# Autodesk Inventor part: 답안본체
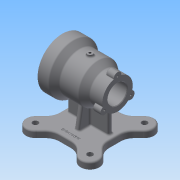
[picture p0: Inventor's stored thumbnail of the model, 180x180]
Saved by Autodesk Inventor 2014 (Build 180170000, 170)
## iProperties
Created: 2017-03
Part Number: 답안본체
Material: 일반
Document SubType Name: Modeling
Designer: NET
Density: 1 g/cm^3
Appearance: 기본값
Author: NET
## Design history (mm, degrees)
sketch "스케치2"
  geometry: L1 (0, 70)-(0, -70); L2 (-70, 0)-(70, 0); L3 (-49.497, -49.497)-(49.497, 49.497); L4 (49.497, -49.497)-(-49.497, 49.497); L5 (-52.322, 28.281)-(-61.518, 37.477); L6 (-28.281, 52.322)-(-37.477, 61.518); L7 (-61.518, -37.477)-(-52.322, -28.281); L8 (-37.477, -61.518)-(-28.281, -52.322); L9 (0, 0)-(45, 0); L10 (0, 0)-(0, -45); L11 (-10.603, 45)-(10.603, 45); L12 (45, 10.603)-(45, -10.603); L13 (10.603, -45)-(-10.603, -45); L14 (-45, -10.603)-(-45, 10.603); L15 (-45, 45)-(45, -45); L16 (45, 45)-(-45, -45); L17 (28.281, 52.322)-(37.477, 61.518); L18 (28.281, -52.322)-(35.995, -60.036); L19 (61.518, -37.477)-(52.322, -28.281); L20 (52.322, 28.281)-(61.518, 37.477); A1 r 17 centre (-49.497, 49.497) between (-36.106, 59.97) and (-59.97, 36.106); A2 r 17 centre (-49.497, -49.497) between (-59.97, -36.106) and (-36.106, -59.97); A3 r 17 centre (49.497, -49.497) between (36.106, -59.97) and (59.97, -36.106); A4 r 17 centre (49.497, 49.497) between (59.97, 36.106) and (36.106, 59.97); A5 r 25 centre (-70, 10.603) between (-45, 10.603) and (-52.322, 28.281); A6 r 25 centre (-70, -10.603) between (-52.322, -28.281) and (-45, -10.603); A7 r 25 centre (-10.603, 70) between (-28.281, 52.322) and (-10.603, 45); A8 r 25 centre (-10.603, -70) between (-10.603, -45) and (-28.281, -52.322); A9 r 25 centre (10.603, 70) between (10.603, 45) and (28.281, 52.322); A10 r 25 centre (10.603, -70) between (28.281, -52.322) and (10.603, -45); A11 r 25 centre (70, -10.603) between (45, -10.603) and (52.322, -28.281); A12 r 25 centre (70, 10.603) between (52.322, 28.281) and (45, 10.603); A13 r 70 centre (0, 0) between (-35.995, 60.036) and (-60.036, 35.995); A14 r 70 centre (0, 0) between (60.036, 35.995) and (35.995, 60.036); A15 r 70 centre (0, 0) between (-60.036, -35.995) and (-35.995, -60.036); A16 r 70 centre (0, 0) between (35.995, -60.036) and (60.036, -35.995); 1 further point
  constraints: 44 point on circle, 40 end point, 18 point on line, 16 centre point, 16 tangent, 10 parallel, 5 coincident, 4 equal radius, 4 midpoint, 2 perpendicular, 1 horizontal, 1 vertical
  dimensions: "d25" = 140 distance of L1.start L1.end; "d26" = 140 distance of L2.start L2.end; "d27" = 45 deg angle of L1 L3; "d28" = 45 deg angle of L1 L4; "d29" = 34 diameter of A1; "d30" = 34 diameter of A2; "d31" = 34 diameter of A3; "d32" = 34 diameter of A4; "d33" = 17 distance between parallel lines of L4 L5; "d34" = 17 distance between parallel lines of L6 L4; "d35" = 17 distance between parallel lines of L7 L3; "d36" = 17 distance between parallel lines of L8 L3; "d37" = 45 distance of L9.start L9.end; "d38" = 45 distance of L9.start L10.end; "d39" = 90 distance of L15.start L16.start; "d40" = 25 radius of A5; "d41" = 17 distance between parallel lines of L19 L4; "d42" = 17 distance between parallel lines of L18 L15; "d43" = 17 distance between parallel lines of L17 L3; "d44" = 25 radius of A9; "d45" = 25 radius of A10; "d46" = 17 distance between parallel lines of L20 L3; "d47" = 25 radius of A12; "d48" = 45 distance between parallel lines of L13 L2; "d49" = 98.99495 horizontal distance of A4.centre A2.centre; "d50" = 98.99495 horizontal distance of A1.centre A3.centre; "d51" = 98.99495 distance of A3.centre A4.centre; "d52" = 70 radius of A16; "d53" = 45 distance between parallel lines of L14 L1
extrude "돌출1" new body sketch "스케치2" distance "d54" = 12; taper "d55" = 0 deg
node "작업 평면1"
sketch "스케치3"
  geometry: L1 (-55.894, 0)-(-55.894, 12) reference; L2 (77.101, 0)-(77.101, 12) reference; L3 (10.603, 0)-(10.603, 82); L4 (10.603, 82)-(-39.397, 82); L5 (-39.397, 82)-(-39.397, 127); L6 (-39.397, 127)-(-19.397, 127); L7 (10.603, 82)-(60.603, 82); L8 (60.603, 82)-(60.603, 109.5); L9 (-39.397, 82)-(-8.397, 82); L10 (-8.397, 118)-(-19.397, 127); L11 (60.603, 109.5)-(37.603, 109.5); L12 (-39.397, 82)-(25.603, 82); L13 (25.603, 118)-(-8.397, 118); L14 (25.603, 118)-(37.603, 109.5); L15 (-39.397, 82)-(-16.397, 82); L16 (-16.397, 82)-(-16.397, 114); L17 (-19.397, 117)-(-39.397, 117); L18 (-8.397, 117)-(-8.397, 118); L19 (60.603, 82)-(30.603, 82); L20 (30.603, 82)-(30.603, 99.5); L21 (33.603, 99.5)-(60.603, 99.5); L22 (-16.397, 82)-(-16.397, 105); L23 (-13.397, 108)-(27.603, 108); L24 (30.603, 105)-(30.603, 82); A1 r 3 centre (-19.397, 114) between (-16.397, 114) and (-19.397, 117); A2 r 3 centre (-13.397, 105) between (-13.397, 108) and (-16.397, 105); A3 r 3 centre (27.603, 105) between (30.603, 105) and (27.603, 108); A4 r 3 centre (33.603, 102.5) between (30.603, 102.5) and (33.603, 99.5); 2 further points
  constraints: 44 end point, 15 point on line, 10 perpendicular, 8 point on circle, 8 tangent, 5 parallel, 4 centre point, 2 equal radius
  dimensions: "d56" = 82 distance of L3.start L3.end; "d57" = 50 distance of L3.end L4.end; "d58" = 45 distance of L4.end L5.end; "d59" = 20 distance of L5.end L6.end; "d60" = 50 distance of L3.end L7.end; "d61" = 27.5 distance of L7.end L8.end; "d62" = 31 distance of L4.end L9.end; "d63" = 36 distance of L9.end L10.start; "d64" = 23 distance of L8.end L11.end; "d65" = 65 distance of L4.end L12.end; "d66" = 23 distance of L4.end L15.end; "d67" = 35 distance of L15.end point (-16.397, 117); "d68" = 36 distance between parallel lines of L12 L13; "d69" = 12 horizontal distance of L13.start L11.end; "d70" = 30 distance of L19.end L7.end; "d71" = 17.5 distance of L19.end L20.end; "d72" = 26 distance of L15.end point (-16.397, 108); "d73" = 3 radius of A1; "d74" = 3 radius of A4
revolve "회전1" sketch "스케치3" stored, may be unused: angle "d75" = 90 deg
sketch "스케치4" dims "d76" = 80
  geometry: C1 r 45 at (0, 0) reference; C2 r 2.5 at (40, 0); C3 r 2.5 at (20, 34.641); C4 r 2.5 at (-20, 34.641); C5 r 2.5 at (-40, 0); C6 r 2.5 at (-20, -34.641); C7 r 2.5 at (20, -34.641); 2 further points
  constraints: 6 centre point, 1 coincident, 1 horizontal alignment, 15 other
  dimensions: "d77" = 5 diameter of C2; "d80" = 360 deg dimension on point (0, 0) C2.centre (derived); "d82" = 34.64102 vertical distance of C2.centre C3.centre
hole "구멍1" sketch "스케치4" at (-40, 0), (-20, -34.641), (20, -34.641), (40, 0), (20, 34.641), (-20, 34.641) diameter "d83" = 3.242; stored, may be unused: countersink angle "d87" = 90 deg, drill point angle "d89" = 118 deg; dims "d84" = 9, "d85" = 4, "d86" = 2, "d88" = 11
node "작업 평면3"
  node "작업 평면2"
sketch "스케치5"
  geometry: C1 r 5 at (0, 0); 1 further point
  constraints: 1 centre point, 1 coincident
  dimensions: "d92" = 10 diameter of C1
extrude "돌출2" join sketch "스케치5" stored distance "d93" = 12; taper "d94" = 0 deg
sketch "스케치6"
  geometry: C1 r 5 at (0, 0) reference; C2 r 2.5 at (0, 0)
  constraints: 1 centre point, 1 coincident
  dimensions: "d95" = 5 diameter of C2
hole "구멍2" sketch "스케치6" at (0, 0) diameter "d96" = 4.134; stored, may be unused: countersink angle "d100" = 90 deg, drill point angle "d102" = 118 deg; dims "d97" = 9, "d98" = 4, "d99" = 2, "d101" = 11
sketch "스케치7"
  geometry: C1 r 7 at (-27.5, 0); C2 r 7 at (13.75, -23.816); C3 r 7 at (13.75, 23.816); 2 further points
  constraints: 3 centre point, 1 horizontal alignment, 8 other
  dimensions: "d103" = 14 diameter of C1; "d106" = 360 deg dimension on point (0, 0) C1.centre (derived); "d108" = 23.8157 vertical distance of C1.centre C2.centre
extrude "돌출3" join sketch "스케치7" distance "d109" = 15; taper "d110" = 0 deg
sketch "스케치8"
  geometry: C1 r 2.5 at (0, 0); C2 r 2.5 at (41.25, 23.816); C3 r 2.5 at (41.25, -23.816); A1 r 7 centre (0, 0) between (0.891, 6.943) and (0.891, -6.943) reference; A2 r 7 centre (41.25, -23.816) between (34.792, -26.516) and (46.817, -19.573) reference; A3 r 7 centre (41.25, 23.816) between (46.817, 19.573) and (34.792, 26.516) reference; 1 further point
  constraints: 3 centre point, 3 coincident
  dimensions: "d111" = 5 diameter of C1; "d112" = 5 diameter of C2; "d113" = 5 diameter of C3
hole "구멍3" sketch "스케치8" at (0, 0), (41.25, -23.816), (41.25, 23.816) diameter "d114" = 3.242; stored, may be unused: countersink angle "d118" = 90 deg, drill point angle "d120" = 118 deg; dims "d115" = 9, "d116" = 4, "d117" = 2, "d119" = 11
sketch "스케치9"
  geometry: L1 (4, 4)-(37, 4); L2 (4, -4)-(37, -4); L3 (4, -4)-(4, -25); L4 (-4, -4)-(-4, -25); L5 (-4, 4)-(-37, 4); L6 (-4, 4)-(-4, 25); L7 (4, 4)-(4, 25); L8 (-4, -4)-(-37, -4); L9 (-37, 4)-(-37, -4); L10 (-4, 25)-(4, 25); L11 (-4, -25)-(4, -25); L12 (37, 4)-(37, -4); A1 r 70 centre (0, 0) between (59.97, -36.106) and (60.036, -35.995) reference; A2 r 70 centre (0, 0) between (35.995, -60.036) and (36.106, -59.97) reference
  constraints: 24 end point, 3 perpendicular, 2 horizontal, 2 vertical, 1 parallel
  dimensions: "d133" = 8 distance between parallel lines of L7 L6; "d134" = 8 distance between parallel lines of L2 L1; "d135" = 8 distance between parallel lines of L3 L4; "d136" = 8 distance between parallel lines of L5 L8; "d137" = 25 distance from line of A2.centre L10; "d138" = 37 distance from line of L12 A1.centre; "d139" = 37 distance from line of L9 A2.centre; "d140" = 4 distance from line of A1.centre L4; "d141" = 25 distance from line of L11 A1.centre; "d142" = 4 distance from line of A1.centre L1; "d143" = 4 distance from line of A1.centre L7; "d144" = 4 distance from line of A2.centre L8
extrude "돌출4" join sketch "스케치9" stored distance "d145" = 15; taper "d146" = 0 deg
feature "면 기울기1" dims angle "d147" = 10 deg
feature "면 기울기2" dims angle "d148" = 10 deg
sketch "스케치10"
  geometry: C1 r 5 at (-49.497, 49.497); C2 r 5 at (49.497, 49.497); C3 r 5 at (-49.497, -49.497); C4 r 5 at (49.497, -49.497); A1 r 17 centre (49.497, -49.497) between (36.106, -59.97) and (59.97, -36.106) reference; A2 r 17 centre (49.497, 49.497) between (59.97, 36.106) and (36.106, 59.97) reference; A3 r 17 centre (-49.497, 49.497) between (-36.106, 59.97) and (-59.97, 36.106) reference; A4 r 17 centre (-49.497, -49.497) between (-59.97, -36.106) and (-36.106, -59.97) reference
  constraints: 4 centre point, 4 coincident
  dimensions: "d149" = 10 diameter of C1; "d150" = 10 diameter of C2; "d151" = 10 diameter of C3; "d152" = 10 diameter of C4
extrude "돌출5" cut sketch "스케치10" stored distance "d153" = 15; taper "d154" = 0 deg
fillet "모깎기1" dims "d155" = 3
fillet "모깎기2" dims "d156" = 3
fillet "모깎기3" dims "d157" = 3
chamfer "모따기1" distance "d159" = 1; stored, may be unused: second distance "d160" = 2, angle "d161" = 45 deg
chamfer "모따기2" distance "d162" = 1; stored, may be unused: second distance "d163" = 2, angle "d164" = 45 deg
fillet "모깎기5" dims "d165" = 3
fillet "모깎기6" dims "d166" = 3
fillet "모깎기7" dims "d167" = 1
fillet "모깎기8" dims "d168" = 3
fillet "모깎기9" dims "d169" = 3
sketch "스케치11"
  geometry: L1 (52.322, 28.281)-(60.036, 35.995) reference; L2 (45, -10.603)-(45, 10.603) reference; L3 (60.036, -35.995)-(52.322, -28.281) reference; L4 (28.281, -52.322)-(35.995, -60.036) reference; L5 (-10.603, -45)-(10.603, -45) reference; L6 (-35.995, -60.036)-(-28.281, -52.322) reference; L7 (-52.322, -28.281)-(-60.036, -35.995) reference; L8 (-45, 10.603)-(-45, -10.603) reference; L9 (-60.036, 35.995)-(-52.322, 28.281) reference; L10 (-28.281, 52.322)-(-35.995, 60.036) reference; L11 (10.603, 45)-(-10.603, 45) reference; L12 (35.995, 60.036)-(28.281, 52.322) reference; L13 (45, 0)-(0, 0); L14 (0, 0)-(0, -35); C1 r 5 at (-49.497, -49.497) reference; C2 r 5 at (-49.497, 49.497) reference; C3 r 5 at (49.497, 49.497) reference; C4 r 5 at (49.497, -49.497) reference; A1 r 17 centre (49.497, 49.497) between (59.97, 36.106) and (36.106, 59.97) reference; A2 r 70 centre (0, 0) between (60.036, 35.995) and (59.97, 36.106) reference; A3 r 25 centre (70, 10.603) between (52.322, 28.281) and (45, 10.603) reference; A4 r 25 centre (70, -10.603) between (45, -10.603) and (52.322, -28.281) reference; A5 r 70 centre (0, 0) between (59.97, -36.106) and (60.036, -35.995) reference; A6 r 17 centre (49.497, -49.497) between (36.106, -59.97) and (59.97, -36.106) reference; A7 r 70 centre (0, 0) between (35.995, -60.036) and (36.106, -59.97) reference; A8 r 25 centre (10.603, -70) between (28.281, -52.322) and (10.603, -45) reference; A9 r 25 centre (-10.603, -70) between (-10.603, -45) and (-28.281, -52.322) reference; A10 r 70 centre (0, 0) between (-36.106, -59.97) and (-35.995, -60.036) reference; A11 r 17 centre (-49.497, -49.497) between (-59.97, -36.106) and (-36.106, -59.97) reference; A12 r 70 centre (0, 0) between (-60.036, -35.995) and (-59.97, -36.106) reference; A13 r 25 centre (-70, -10.603) between (-52.322, -28.281) and (-45, -10.603) reference; A14 r 25 centre (-70, 10.603) between (-45, 10.603) and (-52.322, 28.281) reference; A15 r 70 centre (0, 0) between (-59.97, 36.106) and (-60.036, 35.995) reference; A16 r 17 centre (-49.497, 49.497) between (-36.106, 59.97) and (-59.97, 36.106) reference; A17 r 70 centre (0, 0) between (-35.995, 60.036) and (-36.106, 59.97) reference; A18 r 25 centre (-10.603, 70) between (-28.281, 52.322) and (-10.603, 45) reference; A19 r 25 centre (10.603, 70) between (10.603, 45) and (28.281, 52.322) reference; A20 r 70 centre (0, 0) between (36.106, 59.97) and (35.995, 60.036) reference; 1 further point
  constraints: 4 end point, 1 coincident, 1 midpoint, 1 parallel, 1 perpendicular, 1 other
  dimensions: "d170" = 45 distance of L13.start L13.end (derived); "d171" = 35 distance of L13.end L14.end
feature "엠보싱1" sketch "스케치11" dims "d40" = 25, "d172" = 0.5, "d173" = 0
sketch "스케치13"
  geometry: C1 r 2.067 at (0, 0) reference; C2 r 5 at (0, 0) reference; C3 r 2.5 at (0, 0)
  constraints: 1 centre point, 1 coincident
  dimensions: "d182" = 5 diameter of C3
extrude "돌출6" join sketch "스케치13" stored distance "d183" = 10; taper "d184" = 0 deg
sketch "스케치14"
  geometry: C1 r 5 at (0, 0) reference; C2 r 2.5 at (0, 0)
  constraints: 1 centre point, 1 coincident
  dimensions: "d185" = 5 diameter of C2
hole "구멍5" sketch "스케치14" at (0, 0) diameter "d186" = 4.134; stored, may be unused: countersink angle "d190" = 90 deg, drill point angle "d192" = 118 deg; dims "d187" = 6, "d188" = 4, "d189" = 2, "d191" = 8
node "솔리드1"
node "투영된 루프1"
other parameters: "d90" = -82
